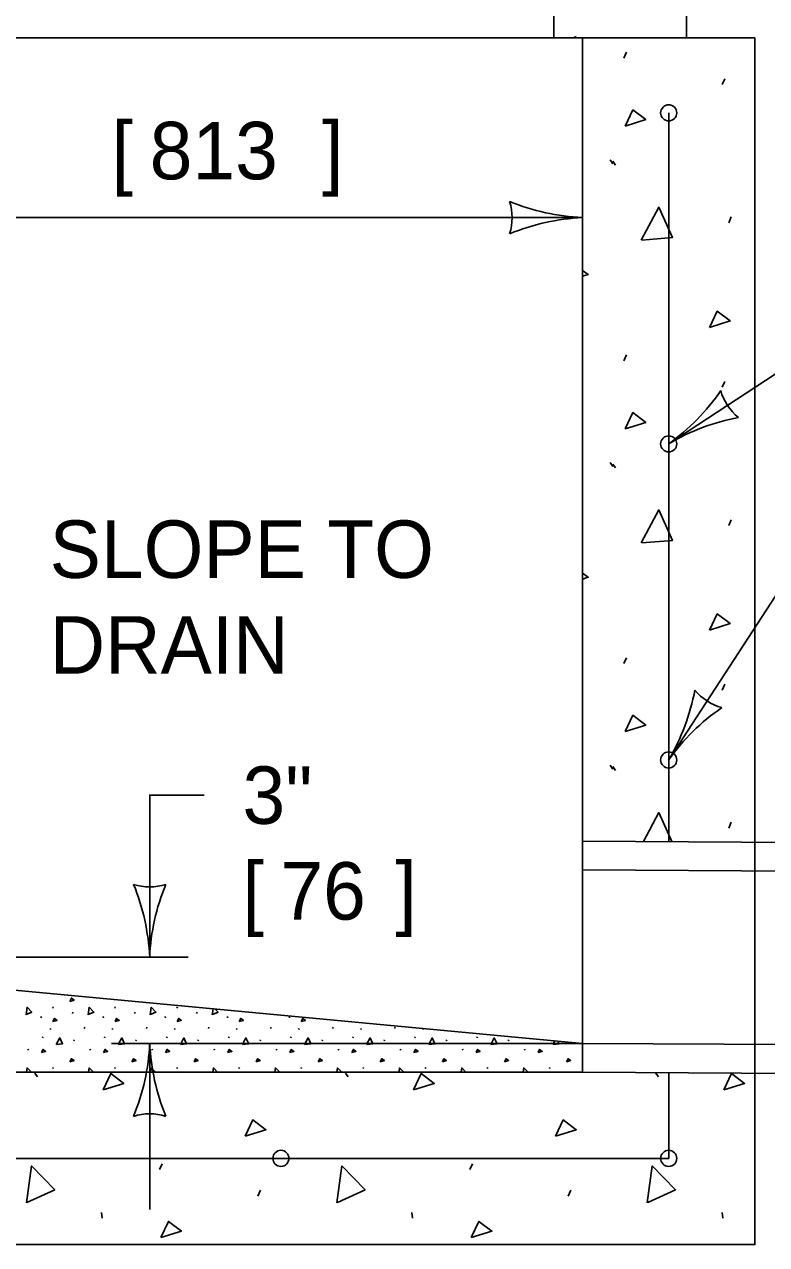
# Model space of a CAD drawing. Extents: x 49991.4 to 50041.6, y 49987.6 to 50011.4.
# Drawn here: x 50038.895 to 50039.67, y 49992.177 to 49993.451 of the extents above; entities that cross this region are included whole.
import ezdxf

# ---------------------------------------------------------------- set-up
doc = ezdxf.new("R2010")
doc.units = 0
for name, color, linetype in [('Level 1', 7, 'Continuous'), ('Level 2', 7, 'Continuous'), ('Level 3', 7, 'Continuous'), ('Level 4', 7, 'Continuous')]:
    doc.layers.add(name, color=color, linetype=linetype)

msp = doc.modelspace()

# ---------------------------------------------------------------- linework, layer by layer
at = {"layer": 'Level 1'}
for p, q in [((50039.521, 49993.4157), (50039.5237, 49993.4218)), ((50039.6239, 49993.388), (50039.6266, 49993.3941)), ((50039.5068, 49993.3095), (50039.5095, 49993.3054)), ((50039.5095, 49993.3079), (50039.5122, 49993.3039)), ((50039.6306, 49993.2437), (50039.6333, 49993.2498)), ((50039.521, 49993.0996), (50039.5237, 49993.1057)), ((50039.6239, 49993.0719), (50039.6266, 49993.078)), ((50039.5068, 49992.9934), (50039.5095, 49992.9893)), ((50039.5095, 49992.9918), (50039.5122, 49992.9878)), ((50039.6306, 49992.9277), (50039.6333, 49992.9337)), ((50039.521, 49992.7835), (50039.5237, 49992.7896)), ((50039.6239, 49992.7558), (50039.6266, 49992.7619)), ((50039.5068, 49992.6773), (50039.5095, 49992.6732)), ((50039.5095, 49992.6758), (50039.5122, 49992.6717)), ((50039.6306, 49992.6116), (50039.6333, 49992.6177)), ((50039.4779, 49992.598), (50040.6924, 49992.5913)), ((50039.4779, 49992.568), (50040.7207, 49992.5611)), ((50038.5179, 49992.4768), (50039.4779, 49992.3868)), ((50039.4779, 49992.3868), (50040.7191, 49992.3799)), ((50038.9061, 49992.3559), (50038.9088, 49992.3519)), ((50039.2303, 49992.3559), (50039.233, 49992.3519)), ((50039.4779, 49992.3568), (50040.6903, 49992.3501)), ((50039.5544, 49992.3559), (50039.5571, 49992.3519)), ((50039.036, 49992.2551), (50039.0388, 49992.2612)), ((50039.3602, 49992.2551), (50039.3629, 49992.2612)), ((50039.1389, 49992.2274), (50039.1416, 49992.2335)), ((50039.463, 49992.2274), (50039.4657, 49992.2335)), ((50038.9756, 49992.2104), (50038.9763, 49992.2043)), ((50039.2998, 49992.2104), (50039.3005, 49992.2043)), ((50039.6239, 49992.2104), (50039.6246, 49992.2043))]:
    msp.add_line(p, q, dxfattribs=at)
msp.add_lwpolyline([(50039.4479, 49993.4368), (50039.4479, 49993.6168), (50039.5866, 49993.6168), (50039.5866, 49993.4368)], close=True, dxfattribs=at)
for points in [[(50039.6579, 49992.3552), (50039.6579, 49992.1768), (50038.3379, 49992.1768), (50038.3379, 49993.4368), (50039.6579, 49993.4368), (50039.6579, 49992.5964)], [(50038.5179, 49993.4368), (50038.5179, 49992.3568), (50039.4779, 49992.3568), (50039.4779, 49993.4368)], [(50039.4696, 49993.4368), (50039.4702, 49993.438), (50039.4719, 49993.4368)], [(50038.4279, 49993.3585), (50038.4279, 49992.2668), (50039.5679, 49992.2668), (50039.5679, 49992.3563)], [(50039.5224, 49993.3447), (50039.5305, 49993.3616), (50039.544, 49993.3514), (50039.5224, 49993.3447)], [(50039.5679, 49992.5975), (50039.5679, 49993.3585)], [(50039.5393, 49993.2255), (50039.5575, 49993.26), (50039.5718, 49993.2282), (50039.5399, 49993.2255)], [(50039.4779, 49993.194), (50039.4838, 49993.1896), (50039.4779, 49993.1878)], [(50039.6105, 49993.1345), (50039.6186, 49993.1514), (50039.6321, 49993.1412), (50039.6105, 49993.1345)], [(50039.5224, 49993.0286), (50039.5305, 49993.0455), (50039.544, 49993.0353), (50039.5224, 49993.0286)], [(50039.5393, 49992.9094), (50039.5575, 49992.9439), (50039.5718, 49992.9121), (50039.5399, 49992.9094)], [(50039.4779, 49992.878), (50039.4838, 49992.8735), (50039.4779, 49992.8717)], [(50039.6105, 49992.8184), (50039.6186, 49992.8353), (50039.6321, 49992.8252), (50039.6105, 49992.8184)], [(50039.5224, 49992.7125), (50039.5305, 49992.7294), (50039.544, 49992.7192), (50039.5224, 49992.7125)], [(50039.5416, 49992.5976), (50039.5575, 49992.6278), (50039.5711, 49992.5975)], [(50038.9772, 49992.3383), (50038.9853, 49992.3553), (50038.9988, 49992.3451), (50038.9772, 49992.3383)], [(50039.3013, 49992.3383), (50039.3094, 49992.3553), (50039.323, 49992.3451), (50039.3013, 49992.3383)], [(50039.6254, 49992.3383), (50039.6336, 49992.3553), (50039.6471, 49992.3451), (50039.6254, 49992.3383)], [(50039.1255, 49992.29), (50039.1336, 49992.3069), (50039.1472, 49992.2967), (50039.1255, 49992.29)], [(50039.4496, 49992.29), (50039.4578, 49992.3069), (50039.4713, 49992.2967), (50039.4496, 49992.29)], [(50038.8971, 49992.2204), (50038.9024, 49992.259), (50038.9267, 49992.234), (50038.8977, 49992.2206)], [(50039.2212, 49992.2204), (50039.2266, 49992.259), (50039.2508, 49992.234), (50039.2219, 49992.2206)], [(50039.5454, 49992.2204), (50039.5507, 49992.259), (50039.575, 49992.234), (50039.546, 49992.2206)], [(50039.0374, 49992.1841), (50039.0455, 49992.201), (50039.0591, 49992.1908), (50039.0374, 49992.1841)], [(50039.3615, 49992.1841), (50039.3697, 49992.201), (50039.3832, 49992.1908), (50039.3615, 49992.1841)]]:
    msp.add_lwpolyline(points, dxfattribs=at)
for centre in [(50039.5679, 49993.3585), (50039.5679, 49993.3585), (50039.5679, 49993.0128), (50039.5679, 49992.6828), (50039.1629, 49992.2668), (50039.5679, 49992.2668), (50039.5679, 49992.2668)]:
    msp.add_circle(centre, 0.0084, dxfattribs=at)
at = {"layer": 'Level 3'}
for p, q in [((50039.5679, 49993.0128), (50039.9422, 49993.258)), ((50039.5679, 49992.6828), (50039.9422, 49993.258)), ((50038.5179, 49993.2491), (50039.4779, 49993.2491)), ((50038.5179, 49992.4768), (50039.0659, 49992.4768)), ((50039.4779, 49992.3868), (50038.9859, 49992.3868)), ((50039.0259, 49992.3868), (50039.0259, 49992.2134))]:
    msp.add_line(p, q, dxfattribs=at)
msp.add_lwpolyline([(50039.0259, 49992.4768), (50039.0259, 49992.6461), (50039.0828, 49992.6461)], dxfattribs=at)
for centre, radius, start, end in [((50039.487, 49993.4713), 0.2223, 247.456, 267.6395), ((50039.3496, 49993.2491), 0.0548, 342.1388, 17.8612), ((50039.4894, 49993.0164), 0.233, 92.8273, 112.0772), ((50039.4308, 49993.2012), 0.233, 306.0479, 325.2978), ((50039.4308, 49993.2012), 0.233, 306.0479, 325.2978), ((50039.6751, 49993.0831), 0.0548, 195.3594, 231.0818), ((50039.6751, 49993.0831), 0.0548, 195.3594, 231.0818), ((50039.6819, 49992.822), 0.2223, 100.6766, 120.8601), ((50039.6819, 49992.822), 0.2223, 100.6766, 120.8601), ((50039.3666, 49992.8002), 0.233, 329.7681, 349.0179), ((50039.3666, 49992.8002), 0.233, 329.7681, 349.0179), ((50039.6378, 49992.7903), 0.0548, 219.0796, 254.802), ((50039.6378, 49992.7903), 0.0548, 219.0796, 254.802), ((50039.749, 49992.554), 0.2223, 124.3968, 144.5803), ((50039.749, 49992.554), 0.2223, 124.3968, 144.5803), ((50039.0259, 49992.605), 0.0548, 252.1388, 287.8612), ((50038.7932, 49992.4653), 0.233, 2.8273, 22.0772), ((50039.248, 49992.4676), 0.2223, 157.456, 177.6395), ((50038.8037, 49992.3959), 0.2223, 337.456, 357.6395), ((50039.2586, 49992.3983), 0.233, 182.8273, 202.0772), ((50039.0259, 49992.2585), 0.0548, 72.1388, 107.8612)]:
    msp.add_arc(centre, radius, start, end, dxfattribs=at)
at = {"layer": 'Level 4'}
for p, q in [((50039.6579, 49992.5964), (50039.6579, 49992.3552)), ((50038.9126, 49992.4148), (50038.9127, 49992.4136)), ((50038.9246, 49992.4238), (50038.9252, 49992.425)), ((50038.9452, 49992.4182), (50038.9458, 49992.4194)), ((50038.9774, 49992.4148), (50038.9775, 49992.4136)), ((50038.9895, 49992.4238), (50038.99, 49992.425)), ((50039.01, 49992.4182), (50039.0106, 49992.4194)), ((50039.0422, 49992.4148), (50039.0424, 49992.4136)), ((50039.0543, 49992.4238), (50039.0548, 49992.425)), ((50039.0749, 49992.4182), (50039.0754, 49992.4194)), ((50039.107, 49992.4148), (50039.1072, 49992.4136)), ((50039.1397, 49992.4182), (50039.1398, 49992.4185)), ((50039.1719, 49992.4148), (50039.172, 49992.4136)), ((50038.9218, 49992.4025), (50038.9223, 49992.4017)), ((50038.9223, 49992.4022), (50038.9229, 49992.4014)), ((50038.9575, 49992.4025), (50038.9581, 49992.4037)), ((50038.9866, 49992.4025), (50038.9872, 49992.4017)), ((50038.9872, 49992.4022), (50038.9877, 49992.4014)), ((50039.0224, 49992.4025), (50039.0229, 49992.4037)), ((50039.0515, 49992.4025), (50039.052, 49992.4017)), ((50039.052, 49992.4022), (50039.0525, 49992.4014)), ((50039.0872, 49992.4025), (50039.0877, 49992.4037)), ((50039.1163, 49992.4025), (50039.1168, 49992.4017)), ((50039.1168, 49992.4022), (50039.1174, 49992.4014)), ((50039.152, 49992.4025), (50039.1526, 49992.4037)), ((50039.1811, 49992.4025), (50039.1817, 49992.4017)), ((50039.1817, 49992.4022), (50039.1822, 49992.4014)), ((50039.2168, 49992.4025), (50039.2174, 49992.4037)), ((50039.2459, 49992.4025), (50039.2465, 49992.4017)), ((50039.2465, 49992.4022), (50039.247, 49992.4014)), ((50039.2817, 49992.4025), (50039.2822, 49992.4037)), ((50039.3108, 49992.4024), (50039.3113, 49992.4017)), ((50039.3113, 49992.4022), (50039.3118, 49992.4014)), ((50038.9138, 49992.3925), (50038.9144, 49992.3937)), ((50038.9466, 49992.3894), (50038.9471, 49992.3906)), ((50038.9786, 49992.3925), (50038.9792, 49992.3937)), ((50039.0114, 49992.3894), (50039.0119, 49992.3906)), ((50039.0435, 49992.3925), (50039.044, 49992.3937)), ((50039.0762, 49992.3894), (50039.0768, 49992.3906)), ((50039.1083, 49992.3925), (50039.1088, 49992.3937)), ((50039.1411, 49992.3894), (50039.1416, 49992.3906)), ((50039.1731, 49992.3925), (50039.1737, 49992.3937)), ((50039.2059, 49992.3894), (50039.2064, 49992.3906)), ((50039.238, 49992.3925), (50039.2385, 49992.3937)), ((50039.2707, 49992.3894), (50039.2712, 49992.3906)), ((50039.3028, 49992.3925), (50039.3033, 49992.3937)), ((50039.3355, 49992.3894), (50039.3361, 49992.3906)), ((50039.3676, 49992.3925), (50039.3681, 49992.3937)), ((50039.4004, 49992.3894), (50039.4009, 49992.3906)), ((50038.8987, 49992.3807), (50038.8992, 49992.3799)), ((50038.9635, 49992.3807), (50038.964, 49992.3799)), ((50039.0283, 49992.3807), (50039.0289, 49992.3799)), ((50039.0931, 49992.3807), (50039.0937, 49992.3799)), ((50039.158, 49992.3807), (50039.1585, 49992.3799)), ((50039.2228, 49992.3807), (50039.2233, 49992.3799)), ((50039.2876, 49992.3807), (50039.2882, 49992.3799)), ((50039.3525, 49992.3807), (50039.353, 49992.3799)), ((50039.4173, 49992.3807), (50039.4178, 49992.3799)), ((50038.9246, 49992.3605), (50038.9252, 49992.3618)), ((50038.9895, 49992.3605), (50038.99, 49992.3618)), ((50039.0543, 49992.3605), (50039.0548, 49992.3618)), ((50039.1191, 49992.3605), (50039.1197, 49992.3618)), ((50039.184, 49992.3605), (50039.1845, 49992.3618)), ((50039.2488, 49992.3605), (50039.2493, 49992.3618)), ((50039.3136, 49992.3605), (50039.3142, 49992.3618)), ((50039.3784, 49992.3605), (50039.379, 49992.3618)), ((50039.4433, 49992.3605), (50039.4438, 49992.3618))]:
    msp.add_line(p, q, dxfattribs=at)
for points in [[(50038.9425, 49992.4307), (50038.9442, 49992.4341), (50038.9469, 49992.4321), (50038.9425, 49992.4307)], [(50039.0074, 49992.4307), (50039.0074, 49992.4309)], [(50039.0077, 49992.4308), (50039.0074, 49992.4307)], [(50038.8969, 49992.4168), (50038.8979, 49992.4246), (50038.9028, 49992.4195), (50038.897, 49992.4169)], [(50038.9617, 49992.4168), (50038.9628, 49992.4246), (50038.9676, 49992.4195), (50038.9618, 49992.4169)], [(50039.0265, 49992.4168), (50039.0276, 49992.4246), (50039.0324, 49992.4195), (50039.0266, 49992.4169)], [(50039.0913, 49992.4168), (50039.0922, 49992.4229)], [(50039.0942, 49992.4227), (50039.0973, 49992.4195), (50039.0915, 49992.4169)], [(50039.1562, 49992.4168), (50039.1562, 49992.4169)], [(50039.1564, 49992.4169), (50039.1563, 49992.4169)], [(50038.9249, 49992.4096), (50038.9265, 49992.4129), (50038.9292, 49992.4109), (50038.9249, 49992.4096)], [(50038.9897, 49992.4096), (50038.9914, 49992.4129), (50038.9941, 49992.4109), (50038.9897, 49992.4096)], [(50039.0546, 49992.4096), (50039.0562, 49992.4129), (50039.0589, 49992.4109), (50039.0546, 49992.4096)], [(50039.1194, 49992.4096), (50039.121, 49992.4129), (50039.1237, 49992.4109), (50039.1194, 49992.4096)], [(50039.1842, 49992.4096), (50039.1858, 49992.4129), (50039.1886, 49992.4109), (50039.1842, 49992.4096)], [(50038.9283, 49992.3857), (50038.932, 49992.3926), (50038.9348, 49992.3863), (50038.9284, 49992.3857)], [(50038.9931, 49992.3857), (50038.9968, 49992.3926), (50038.9996, 49992.3863), (50038.9933, 49992.3857)], [(50039.058, 49992.3857), (50039.0616, 49992.3926), (50039.0645, 49992.3863), (50039.0581, 49992.3857)], [(50039.1228, 49992.3857), (50039.1264, 49992.3926), (50039.1293, 49992.3863), (50039.1229, 49992.3857)], [(50039.1876, 49992.3857), (50039.1913, 49992.3926), (50039.1941, 49992.3863), (50039.1877, 49992.3857)], [(50039.2524, 49992.3857), (50039.2561, 49992.3926), (50039.2589, 49992.3863), (50039.2526, 49992.3857)], [(50039.3173, 49992.3857), (50039.3209, 49992.3926), (50039.3238, 49992.3863), (50039.3174, 49992.3857)], [(50039.3821, 49992.3857), (50039.3857, 49992.3926), (50039.3886, 49992.3863), (50039.3822, 49992.3857)], [(50039.4469, 49992.3857), (50039.4489, 49992.3895)], [(50039.4521, 49992.3892), (50039.4534, 49992.3863), (50039.4471, 49992.3857)], [(50038.9129, 49992.3772), (50038.9145, 49992.3806), (50038.9172, 49992.3785), (50038.9129, 49992.3772)], [(50038.9777, 49992.3772), (50038.9793, 49992.3806), (50038.982, 49992.3785), (50038.9777, 49992.3772)], [(50039.0425, 49992.3772), (50039.0441, 49992.3806), (50039.0469, 49992.3785), (50039.0425, 49992.3772)], [(50039.1074, 49992.3772), (50039.109, 49992.3806), (50039.1117, 49992.3785), (50039.1074, 49992.3772)], [(50039.1722, 49992.3772), (50039.1738, 49992.3806), (50039.1765, 49992.3785), (50039.1722, 49992.3772)], [(50039.237, 49992.3772), (50039.2386, 49992.3806), (50039.2413, 49992.3785), (50039.237, 49992.3772)], [(50039.3018, 49992.3772), (50039.3035, 49992.3806), (50039.3062, 49992.3785), (50039.3018, 49992.3772)], [(50039.3667, 49992.3772), (50039.3683, 49992.3806), (50039.371, 49992.3785), (50039.3667, 49992.3772)], [(50039.4315, 49992.3772), (50039.4331, 49992.3806), (50039.4358, 49992.3785), (50039.4315, 49992.3772)], [(50038.9425, 49992.3675), (50038.9442, 49992.3709), (50038.9469, 49992.3689), (50038.9425, 49992.3675)], [(50039.0074, 49992.3675), (50039.009, 49992.3709), (50039.0117, 49992.3689), (50039.0074, 49992.3675)], [(50039.0722, 49992.3675), (50039.0738, 49992.3709), (50039.0765, 49992.3689), (50039.0722, 49992.3675)], [(50039.137, 49992.3675), (50039.1386, 49992.3709), (50039.1413, 49992.3689), (50039.137, 49992.3675)], [(50039.2018, 49992.3675), (50039.2035, 49992.3709), (50039.2062, 49992.3689), (50039.2018, 49992.3675)], [(50039.2667, 49992.3675), (50039.2683, 49992.3709), (50039.271, 49992.3689), (50039.2667, 49992.3675)], [(50039.3315, 49992.3675), (50039.3331, 49992.3709), (50039.3358, 49992.3689), (50039.3315, 49992.3675)], [(50039.3963, 49992.3675), (50039.398, 49992.3709), (50039.4007, 49992.3689), (50039.3963, 49992.3675)], [(50039.4612, 49992.3675), (50039.4628, 49992.3709), (50039.4655, 49992.3689), (50039.4612, 49992.3675)], [(50038.8973, 49992.3568), (50038.8979, 49992.3613), (50038.9024, 49992.3568)], [(50038.9621, 49992.3568), (50038.9628, 49992.3613), (50038.9672, 49992.3568)], [(50039.0269, 49992.3568), (50039.0276, 49992.3613), (50039.032, 49992.3568)], [(50039.0918, 49992.3568), (50039.0924, 49992.3613), (50039.0968, 49992.3568)], [(50039.1566, 49992.3568), (50039.1572, 49992.3613), (50039.1617, 49992.3568)], [(50039.2214, 49992.3568), (50039.2221, 49992.3613), (50039.2265, 49992.3568)], [(50039.2863, 49992.3568), (50039.2869, 49992.3613), (50039.2913, 49992.3568)], [(50039.3511, 49992.3568), (50039.3517, 49992.3613), (50039.3561, 49992.3568)], [(50039.4159, 49992.3568), (50039.4165, 49992.3613), (50039.421, 49992.3568)]]:
    msp.add_lwpolyline(points, dxfattribs=at)

# ---------------------------------------------------------------- texts
at = {"layer": 'Level 2'}
for s, p in [('[', (50038.9862, 49993.2891)), ('813', (50039.0259, 49993.2891)), (']', (50039.2059, 49993.2891)), ('SLOPE TO', (50038.9214, 49992.8729)), ('DRAIN', (50038.9214, 49992.7729)), ('3"', (50039.1228, 49992.6161)), ('[', (50039.1228, 49992.5161)), ('76', (50039.1624, 49992.5161)), (']', (50039.2824, 49992.5161))]:
    msp.add_text(s, height=0.06, rotation=360, dxfattribs=at).set_placement(p)

doc.saveas('drawing.dxf')
